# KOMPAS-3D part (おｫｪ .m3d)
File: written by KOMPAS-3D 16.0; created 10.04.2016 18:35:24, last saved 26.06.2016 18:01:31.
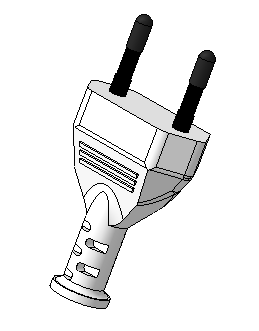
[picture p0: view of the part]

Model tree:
1. Эскиз:2
2. Операция выдавливания:1
     Расстояние 1 = 9
3. Операция выдавливания:2
     Расстояние 1 = 18; Угол 1 = 21
4. Плоскость через два ребра:2
5. Эскиз:3
6. Ось пересечения двух плоскостей:1
7. Вырезать элемент вращения:2
     Угол 1 = 360
8. Эскиз:4
9. Операция выдавливания:3
     Расстояние 1 = 10; Расстояние 2 = 27
10. Скругление:1
     Радиус = 5
11. Скругление:2
     Радиус = 6
12. Операция выдавливания:4
     Расстояние 1 = 17; Расстояние 2 = 27
13. Скругление:3
     Радиус = 3
14. Эскиз:5
15. Операция выдавливания:5
     Расстояние 1 = 4; Расстояние 2 = 27
16. Эскиз:6
17. Операция выдавливания:6
     Расстояние 1 = 7; Расстояние 2 = 27
18. Эскиз:7
19. Операция выдавливания:7
     Расстояние 1 = 8.5; Расстояние 2 = 27
20. Скругление:4
     Радиус = 2
21. Эскиз:8
22. Операция выдавливания:8
     Расстояние 1 = 2; Расстояние 2 = 27
23. Скругление:5
     Радиус = 1.5
24. Эскиз:9
25. Операция выдавливания:9
     Расстояние 1 = 0.5; Расстояние 2 = 18.7974
26. Эскиз:10
27. Операция выдавливания:10
     Расстояние 1 = 0.5; Расстояние 2 = 18.7974
28. Нормальная плоскость:2
29. Смещенная плоскость:1
     Расстояние = 5
30. Эскиз:11
31. Вырезать элемент выдавливания:1
     Расстояние 1 = 2.8038
32. Массив по концентрической сетке:1  (with: Эскиз:11, Вырезать элемент выдавливания:1)  (labels: v406_1_2_v355; v406_1_2_v379; v406_1_2_v380; Толщина стенки 1)  (2 pattern instances)
     Шаг 2 = 360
